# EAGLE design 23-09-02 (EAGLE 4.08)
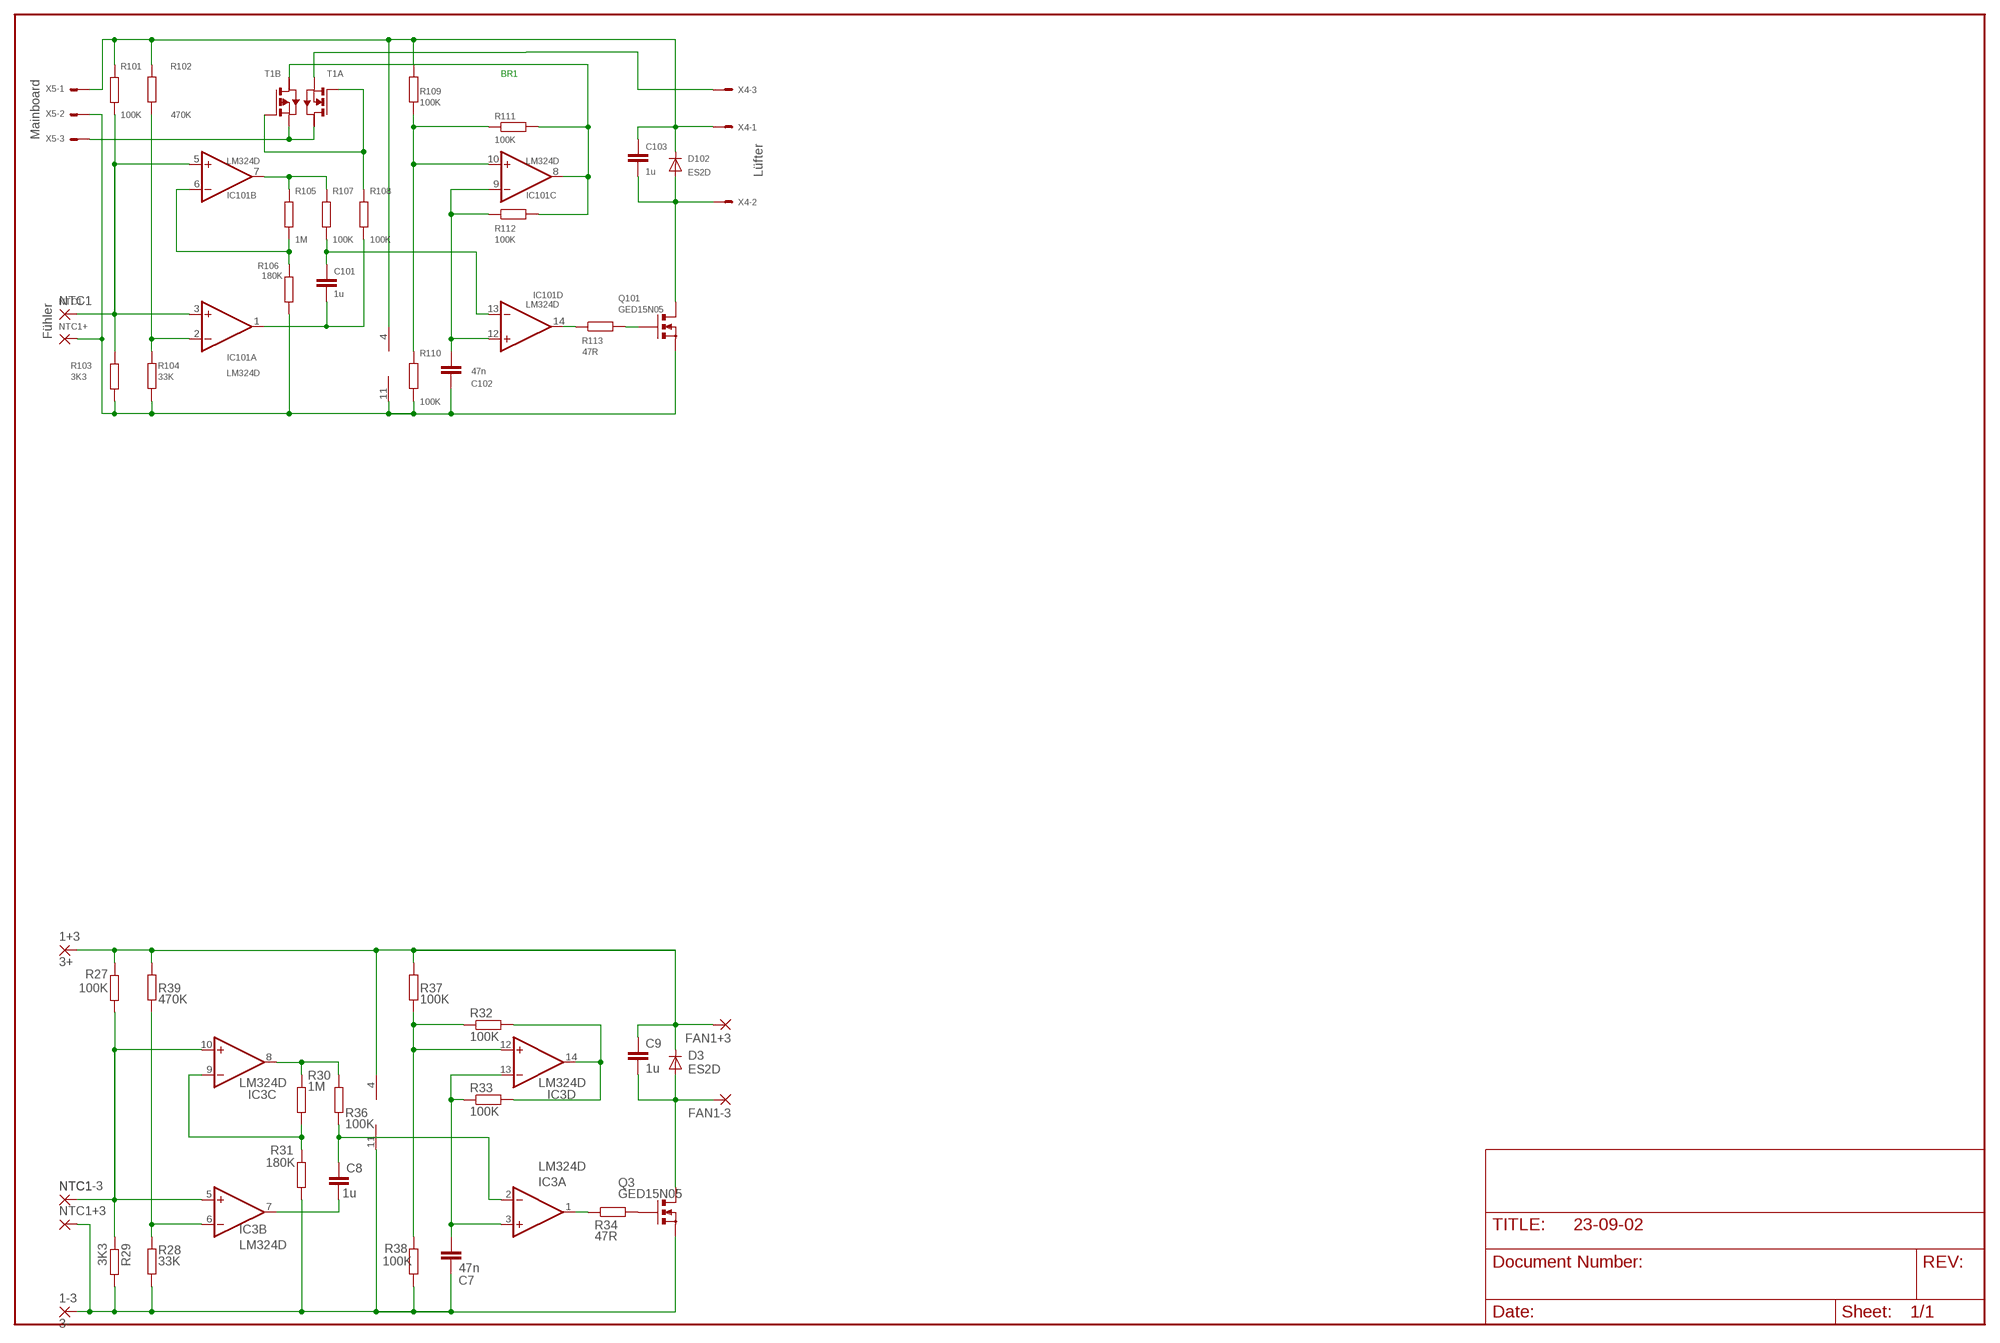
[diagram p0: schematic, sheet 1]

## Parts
1+3  3+  SMD2  [SMD2]
1-3  3-  SMD2  [SMD2]
BR1  BR  [C1206]
C7  47n  C-EUC0805  [C0805]
C8  1u  C-EU  [2220]
C9  1u  C-EU  [2220]
C101  1u  C-EU  [2220]
C102  47n  C-EUC1206  [C1206]
C103  1u  C-EU  [2220]
D3  ES2D  DIODE-SMB  [SMB]
D102  ES2D  DIODE-SMB  [SMB]
FAN1+3  SMD2  [SMD2]
FAN1-3  SMD2  [SMD2]
IC3  LM324D  [SO14]
IC101  LM324D  [SO14]
NTC1+  SMD2  [SMD2]
NTC1+3  SMD2  [SMD2]
NTC1-  NTC1  SMD2  [SMD2]
NTC1-3  NTC1  SMD2  [SMD2]
Q3  GED15N05  [TO252]
Q101  GED15N05  [TO252]
R27  100K  R-EU_M1206  [M1206]
R28  33K  R-EU_M1206  [M1206]
R29  3K3  R-EU_M1206  [M1206]
R30  1M  R-EU_R1206W  [R1206W]
R31  180K  R-EU_R1206W  [R1206W]
R32  100K  R-EU_M0805  [M0805]
R33  100K  R-EU_M0805  [M0805]
R34  47R  R-EU_M1206  [M1206]
R36  100K  R-EU_M1206  [M1206]
R37  100K  R-EU_M0805  [M0805]
R38  100K  R-EU_M0805  [M0805]
R39  470K  R-EU_M1206  [M1206]
R101  100K  R-EU_M1206  [M1206]
R102  470K  R-EU_M1206  [M1206]
R103  3K3  R-EU_M1206  [M1206]
R104  33K  R-EU_M1206  [M1206]
R105  1M  R-EU_R1206  [R1206]
R106  180K  R-EU_M1206  [M1206]
R107  100K  R-EU_M1206  [M1206]
R108  100K  R-EU_M1206  [M1206]
R109  100K  R-EU_M1206  [M1206]
R110  100K  R-EU_M1206  [M1206]
R111  100K  R-EU_M1206  [M1206]
R112  100K  R-EU_M1206  [M1206]
R113  47R  R-EU_M1206  [M1206]
T1  PN_MOSOP8  [MSOP8]
X4  53398-03  [53398-03]
X5  53398-03  [53398-03]

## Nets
N$2: T1.1(A:S) T1.3(B:D) X5.3
N$3: IC3.5(B:+IN) IC3.10(C:+IN) NTC1-3.1(P) R27.2 R29.1
N$4: C102.1 IC101.11(P:V-) NTC1+.1(P) Q101.S R103.2 R104.1 R106.2 R110.1 X5.2
N$24: C103.P$1 D102.C IC101.4(P:V+) R101.1 R102.2 R109.2 X4.1 X5.1
N$37: C103.P$2 D102.A Q101.D X4.2
N$44: IC101.3(A:+IN) IC101.5(B:+IN) NTC1-.1(P) R101.2 R103.1
N$46: C101.P$2 IC101.13(D:-IN) R107.2
N$47: IC101.8(C:OUT) R111.2 R112.2 T1.7(A:D)
N$64: C8.P$2 IC3.2(A:-IN) R36.2
N$66: C101.P$1 IC101.1(A:OUT) R108.2
N$72: IC3.6(B:-IN) R28.2 R39.1
N$73: C8.P$1 IC3.7(B:OUT)
N$74: IC3.8(C:OUT) R30.1 R36.1
N$75: IC3.9(C:-IN) R30.2 R31.1
N$76: IC3.14(D:OUT) R32.2 R33.2
N$77: IC3.12(D:+IN) R32.1 R37.1 R38.2
N$78: C7.2 IC3.3(A:+IN) IC3.13(D:-IN) R33.1
N$79: IC3.1(A:OUT) R34.1
N$81: Q3.G R34.2
N$82: BR1.1 T1.6(B:S)
N$83: 1+3.1(P) C9.P$1 D3.C FAN1+3.1(P) IC3.4(P:V+) R27.1 R37.2 R39.2
N$84: C9.P$2 D3.A FAN1-3.1(P) Q3.D
N$85: 1-3.1(P) C7.1 IC3.11(P:V-) NTC1+3.1(P) Q3.S R28.1 R29.2 R31.2 R38.1
N$86: BR1.2 X4.3
N$98: R108.1 T1.2(A:G) T1.5(B:G)
N$128: IC101.2(A:-IN) R102.1 R104.2
N$130: IC101.7(B:OUT) R105.1 R107.1
N$132: IC101.6(B:-IN) R105.2 R106.1
N$136: IC101.10(C:+IN) R109.1 R110.2 R111.1
N$138: IC101.14(D:OUT) R113.1
N$139: C102.2 IC101.9(C:-IN) IC101.12(D:+IN) R112.1
N$141: Q101.G R113.2
Unconnected: T1.4(B:D2) T1.8(A:D2)

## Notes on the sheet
- Mainboard
- Lüfter
- Fühler

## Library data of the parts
1+3 1-3 FAN1+3 FAN1-3 NTC1+ NTC1+3 NTC1- NTC1-3 = wirepad:SMD2: SMD PAD
BR1 = rcl:BR
C7-C9 C101-C103 = rcl:C-EU: CAPACITOR, European symbol
D3 D102 = diode:DIODE-: DIODE
IC3 IC101 = linear:LM324: OP AMP
Q3 Q101 = transistor-fet:GED15N05
R27-R34 R36-R39 R101-R113 = rcl:R-EU_: RESISTOR, European symbol
T1 = zetex:PN_MOSOP8: Dual MOS FET
X4 X5 = con-molex:53?-03: CONNECTOR wire to board 1.25 mm (.049 inch) pitch header

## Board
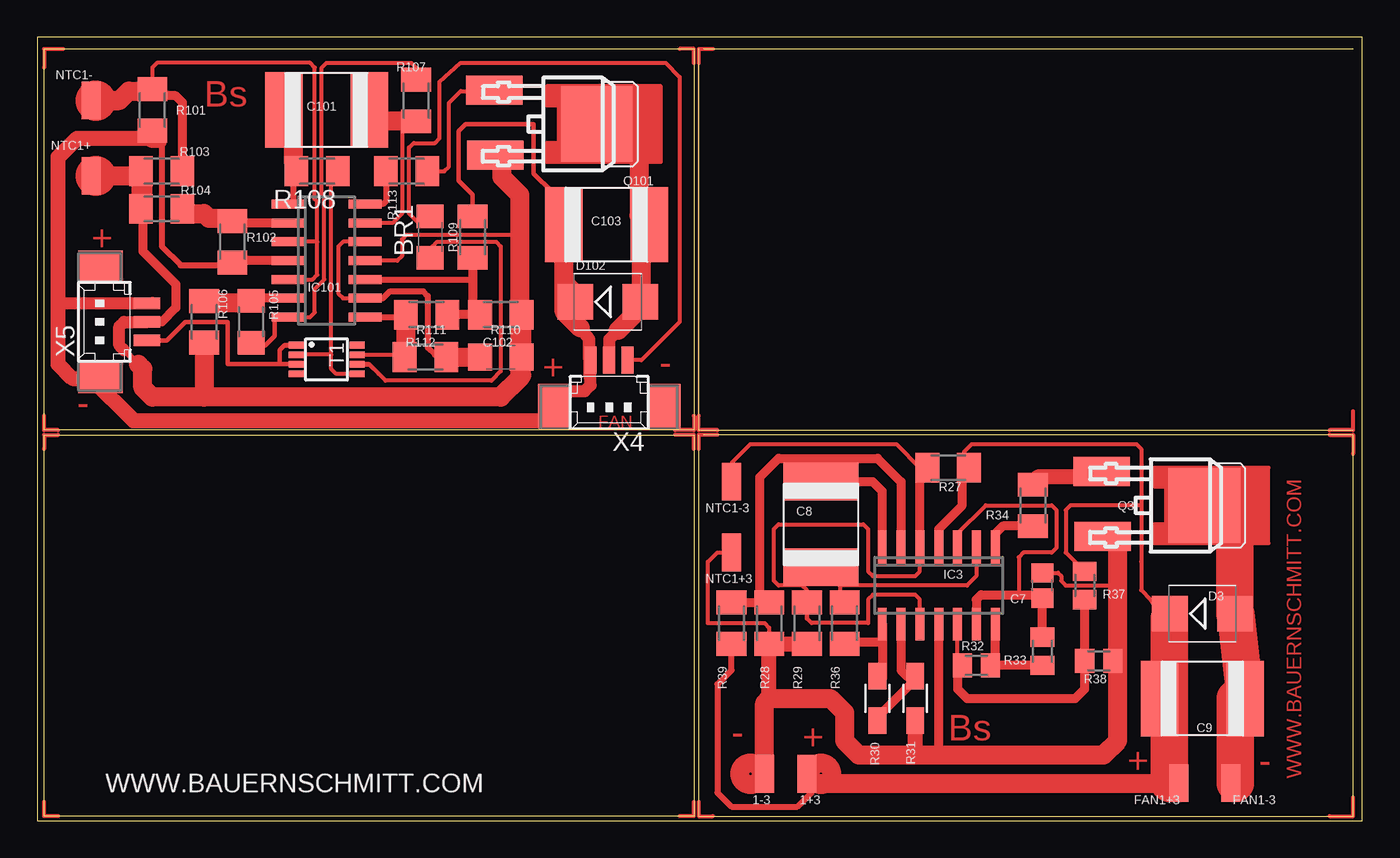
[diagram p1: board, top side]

Size 89.36 x 52.85 mm. Coordinates in mm from the lower left corner, seen from the top.
Outline: 44.92,52.07 88.73,52.07
Outline: 44.6,52.07 44.6,26.35 88.73,26.35
Outline: 44.6,26.03 44.6,0.31 88.73,0.31 88.73,26.03 44.92,26.03
Outline: 0,0 89.36,0 89.36,52.85 0,52.85 0,0
Outline: 44.28,26.03 44.28,0.31 0.47,0.31 0.47,26.03 44.28,26.03
Outline: 44.28,52.07 44.28,26.35 0.47,26.35 0.47,52.07 44.28,52.07
Copper layers used: Top

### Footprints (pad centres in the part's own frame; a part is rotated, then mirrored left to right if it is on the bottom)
SMD2 = smd 1.27 x 2.54: 1 0,0
C1206 = smd 1.6 x 1.8: 1 -1.4,0; 2 1.4,0
C0805 = smd 1.3 x 1.5: 1 -0.85,0; 2 0.85,0
2220 = smd 2.54 x 5.08: P$1 -2.885,0; P$2 2.885,0
SMB = smd 2.4 x 2.4: A 2.2,0; C -2.2,0
SO14 = smd 0.6 x 2.2: 1 -3.81,-2.6; 2 -2.54,-2.6; 3 -1.27,-2.6; 4 0,-2.6; 5 1.27,-2.6; 6 2.54,-2.6; 7 3.81,-2.6; 8 3.81,2.6; 9 2.54,2.6; 10 1.27,2.6; 11 0,2.6; 12 -1.27,2.6; 13 -2.54,2.6; 14 -3.81,2.6
TO252 = smd 5.08 x 2.54: D 0,6.032; GED15N05 0,3.747 | smd 1.016 x 0.508: G -2.032,-1.778; P$9 -2.032,-0.762; P$16 -2.032,-1.27; P$18 -2.032,-2.286; P$19 -2.032,-2.54; P$20 2.032,-0.762; P$21 2.032,-1.016; P$23 2.032,-2.032; P$24 2.032,-2.286; P$25 2.032,-2.54; S 2.032,-1.524 | smd 0.254 x 0.152: P$3 -2.54,-0.508; P$4 2.54,-0.508; P$5 -2.286,-0.508; P$6 -2.032,-0.508; P$7 -1.778,-0.508; P$10 2.286,-0.508; P$11 2.032,-0.508; P$12 1.778,-0.508; P$13 1.524,-0.508; P$15 -2.794,-0.508 | smd 1.93 x 3.81: P$8 -2.286,-2.032; P$14 2.095,-1.968
M1206 = smd 1.6 x 2: 1 -1.4,0; 2 1.4,0
R1206W = smd 1.8 x 1.2: 1 -1.499,0; 2 1.499,0
M0805 = smd 1.3 x 1.6: 1 -0.95,0; 2 0.95,0
R1206 = smd 1.6 x 1.803: 1 -1.422,0; 2 1.422,0
MSOP8 = smd 0.45 x 1: 1 -0.975,-2.05; 2 -0.325,-2.05; 3 0.325,-2.05; 4 0.975,-2.05; 5 0.975,2.05; 6 0.325,2.05; 7 -0.325,2.05; 8 -0.975,2.05
53398-03 = smd 0.8 x 1.8: 1 1.25,-2.5; 2 0,-2.5; 3 -1.25,-2.5 | smd 2.1 x 3: S1 3.75,0.625; S2 -3.75,0.625

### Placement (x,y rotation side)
1+3  51.9,3.17 0 top
1-3  49.05,3.17 0 top
BR1  26.5,39.37 90 top
C7  67.78,15.87 270 top
C8  52.86,20 270 top
C9  78.58,8.25 0 top
C101  19.52,47.94 0 top
C102  31.27,31.27 180 top
C103  38.39,40.2 0 top
D3  78.58,13.97 0 top
D102  38.48,35 0 top
FAN1+3  76.99,2.54 0 top
FAN1-3  80.48,2.54 0 top
IC3  60.79,15.87 180 top
IC101  19.52,37.78 270 top
NTC1+  3.65,43.49 0 top
NTC1+3  46.82,18.09 0 top
NTC1-  3.65,48.57 0 top
NTC1-3  46.82,22.86 0 top
Q3  73.81,21.27 270 top
Q101  32.85,46.98 270 top
R27  61.43,23.81 180 top
R28  49.36,13.33 90 top
R29  51.9,13.33 270 top
R30  56.67,8.25 270 top
R31  59.21,8.25 270 top
R32  63.33,10.47 0 top
R33  67.78,11.43 270 top
R34  67.15,21.27 90 top
R36  54.45,13.33 90 top
R37  70.64,15.87 90 top
R38  71.59,10.79 180 top
R39  46.82,13.33 270 top
R101  7.77,47.94 90 top
R102  13.17,39.05 270 top
R103  8.41,43.81 180 top
R104  8.41,41.27 0 top
R105  14.44,33.65 90 top
R106  11.27,33.65 270 top
R107  25.55,48.57 270 top
R108  18.89,43.81 180 top
R109  29.36,39.37 90 top
R110  31.27,34.13 180 top
R111  26.26,34.13 180 top
R112  26.19,31.27 180 top
R113  24.92,43.81 0 top
T1  19.52,31.11 270 top
X4  38.57,28.57 180 top
X5  4.92,33.65 90 top

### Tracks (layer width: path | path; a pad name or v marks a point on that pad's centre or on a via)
N$2
  Top 0.305: X5.3 8.74,32.4 10,33.65 12.85,33.65 12.85,30.79 16.34,30.79 | 17.62,30.79 17.3,30.79 | 16.34,31.74 16.66,32.06 17.62,32.06 17.59,32.09 T1.1 16.68,32.09 16.34,31.74 | 16.34,31.74 16.34,30.79 | 17.3,30.79 T1.3 | 16.34,30.79 17.3,30.79
N$3
  Top 0.254: R29.1 51.9,13.65 | NTC1-3.1 46.82,24.12 48.09,25.39 57.94,25.39 59.52,23.81 | 59.52,13.33 59.52,14.92 59.21,15.24 56.35,15.24 56.03,14.92 56.03,13.33 52.22,13.33 51.9,13.65 | 51.9,13.65 51.9,15.55 51.59,15.87 50,15.87 49.68,16.19 49.68,19.68 50,20 55.71,20 56.03,19.68 56.03,16.82 56.35,16.5 59.21,16.5 59.52,16.82 59.52,18.41
  Top 0.61: IC3.10 59.52,13.33 | IC3.5 59.52,18.73 | R27.2 59.52,23.81 IC3.5 | IC3.5 59.52,18.41
N$4
  Top 0.254: 32.54,39.52 24.92,39.52 24.6,39.21 24.6,38.1 24.28,37.78 IC101.11
  Top 0.406: 32.54,39.52 32.85,38.73 32.54,38.73 | 22.06,37.78 IC101.11 | 5.87,31.74 6.82,30.79
  Top 0.61: 7.14,41.27 7.14,38.41 9.36,36.19 9.36,34.6 8.41,33.65 7.46,33.65
  Top 0.813: 5.87,33.65 X5.2 7.46,33.65 5.87,33.65 | 5.87,33.65 5.55,33.33 5.55,32.06 5.87,31.74
  Top 1.016: R106.2 11.27,32.38
  Top 1.27: R103.2 7.01,41.78 6.82,41.59 7.01,41.4 R104.1 7.14,41.27 7.14,43.49 NTC1+.1 | Q101.S 31.33,43.43 32.54,42.22 32.54,39.52 | 32.54,39.52 32.54,38.73 32.54,31.43 | C102.1 32.67,34.41 32.54,34.29 32.67,34.16 R110.1 | 31.27,28.57 11.27,28.57 | 11.27,32.38 11.27,28.57 | 11.27,28.57 7.77,28.57 | 32.54,31.43 32.54,29.84 | 32.54,31.43 C102.1 | 32.54,29.84 32.67,30.03 32.67,30.61 | C102.1 32.67,30.61 | 32.67,30.61 32.54,29.84 | 32.54,39.52 32.54,29.84 | 32.54,29.84 31.27,28.57 | 31.27,28.57 7.77,28.57 | 7.77,28.57 7.14,29.2 7.14,30.47 6.82,30.79
N$6
  Top 0: 0.47,52.07 44.28,52.07 44.28,26.35 0.47,26.35 0.47,52.07
  Top 0.254: 0.47,50.8 0.47,52.07 1.74,52.07 | 44.28,27.3 44.28,26.35 43.01,26.35
N$11
  Top 0: 44.6,52.07 44.6,26.35 88.73,26.35
  Top 0.254: 45.55,52.07 44.6,52.07 44.6,51.11 | 87.15,26.35 88.73,26.35 88.73,27.62
N$12
  Top 0.254: 44.28,51.11 44.28,52.07 43.33,52.07
N$14
  Top 0.254: 44.28,25.08 44.28,26.03 43.01,26.03
N$16
  Top 0.254: 45.87,26.35 44.6,26.35 44.6,27.3
N$18
  Top 0: 44.6,26.03 44.6,0.31 88.73,0.31 88.73,26.03 44.6,26.03
  Top 0.254: 45.87,26.03 44.6,26.03 44.6,25.08 | 87.15,0.31 88.73,0.31 88.73,1.58
N$21
  Top 0.254: 44.6,1.27 44.6,0.31 45.55,0.31
N$22
  Top 0.254: 1.42,0.31 0.47,0.31 0.47,1.27
N$23
  Top 0: 44.28,0.31 44.28,26.03 0.47,26.03 0.47,0.31
  Top 0.254: 0.47,25.08 0.47,26.03 1.42,26.03 | 44.28,1.27 44.28,0.31 43.33,0.31
N$24
  Top 0.254: 8.41,45.72 8.41,46.03 8.09,46.03 | 7.77,34.92 7.75,34.9 X5.1 | 37.3,32.38 37.32,32.38 37.22,32.48 | 13.17,37.46 R102.2
  Top 0.305: R109.2 29.36,42.22 28.41,43.18 28.41,46.51 28.89,46.98 33.49,46.98 33.49,43.65 34.76,42.38 34.76,40.95 35.08,40.64 34.97,40.53 34.91,40.53
  Top 0.406: 8.41,45.72 8.41,38.73 9.68,37.46 13.17,37.46
  Top 0.61: 8.09,46.03 8.41,45.72 | R102.2 13.17,37.78 IC101.4
  Top 0.813: 37.32,31.09 X4.1 | 37.32,31.09 37.22,31.09 37.22,32.48 | 37.22,32.48 36.61,33.24 | 37.22,32.48 37.22,29.99 | 37.32,31.09 37.32,29.38 36.92,28.98 35.39,28.98 35.39,28.89 | 1.42,34.92 7.77,34.92
  Top 1.016: 2.69,46.03 7.77,46.03 | 35.39,28.89 35.08,28.57 35.08,27.62 34.44,26.98 6.5,26.98 3.65,29.84 2.38,29.84 1.42,30.79 1.42,34.92 1.42,44.76 2.69,46.03 | 2.69,46.03 8.09,46.03
  Top 1.27: 8.09,46.03 7.77,46.03 7.96,46.22 R101.1 | C103.P$1 34.87,40.62 34.94,40.56 34.91,40.53 35.55,40.53 35.55,36.29 | 35.55,36.29 35.55,35.53 36.16,35.53 36.16,35.63 D102.C 36.28,35.56 35.55,36.29 | 36.61,33.24 35.55,34.31 35.55,36.29
N$25
  Top 0.254: 1.42,26.35 0.47,26.35 0.47,27.3
N$36
  Top 0.254: 87.15,26.03 88.73,26.03 88.73,24.76
N$37
  Top 0.813: X4.2 38.59,31.07 38.59,32.48 39.2,33.09
  Top 1.27: Q101.D 40.58,47.94 40.58,40.84 C103.P$2 40.73,40.84 40.73,35.68 | 40.73,35.68 40.73,35.63 D102.A 40.68,35.63 40.73,35.68 | 39.2,33.09 40.73,34.62 40.73,35.68
N$44
  Top 0.254: IC101.5 18.57,36.51 18.89,36.83 18.89,39.05 | 18.89,39.05 IC101.3 | 18.89,39.05 | 18.89,39.05 18.89,41.75 18.73,41.91 18.73,50.8 18.41,51.11 8.09,51.11 7.77,50.8 7.77,49.53
  Top 0.61: R103.1 9.81,48.44 9.36,48.89 5.87,48.89 3.96,48.89 NTC1-.1
  Top 1.27: R101.2 7.77,49.53 7.46,49.21 6.19,49.21 5.87,48.89 5.55,48.57 NTC1-.1
N$46
  Top 0.254: C101.P$2 22.41,47.33 22.38,47.3 24.6,47.3 24.6,40.95 23.96,40.32 IC101.13 21.74,40.32
  Top 0.406: IC101.13 22.06,40.32
  Top 1.27: C101.P$2 22.41,47.65 22.38,47.62 22.82,47.17 R107.2
N$47
  Top 0.254: 24.91,32.07 24.91,31.75 24.92,31.74 24.61,31.43 T1.7
  Top 0.406: 24.91,32.07 24.92,32.06 24.92,33.97 | R111.2 24.92,34.29 24.92,33.97 | IC101.8 24.92,33.97 | 24.92,33.97 24.92,31.74 24.92,31.43
  Top 1.27: R112.2 24.92,31.43 24.86,31.48 R111.2
N$64
  Top 0.254: IC3.2 63.33,16.5 62.7,15.87 54.13,15.87 | 54.13,17.46 52.86,17.46 C8.P$2 52.88,17.43 54.1,17.43 54.13,17.46 | 54.13,17.46 54.13,15.87 | R36.2 54.45,14.28 54.13,14.6 54.13,15.87
N$66
  Top 0.254: 17.3,47.94 C101.P$1
  Top 0.406: IC101.1 17.3,41.59 17.3,43.49 17.62,43.81 R108.2
  Top 1.27: R108.2 17.3,44.45 17.3,47.94
N$72
  Top 0.61: 58.25,18.41 IC3.6 58.25,22.86 56.67,24.44 50,24.44 48.73,23.17 48.73,14.6 | R39.1 48.6,14.73 48.73,14.6 | 48.73,14.6 R28.2
N$73
  Top 0.61: IC3.7 56.98,22.22 56.35,22.86 52.54,22.86 C8.P$1
N$74
  Top 0.61: 56.98,13.33 IC3.8 56.98,12.06 | 56.98,12.06 56.98,9.52 56.9,9.43 R30.1 56.67,9.52 56.98,9.84 56.98,12.06 | R36.1 54.45,12.06 56.98,12.06
N$75
  Top 0.61: R30.2 56.67,6.98 59.02,9.33 R31.1 59.21,9.2 58.25,10.16 IC3.9
N$76
  Top 0.61: 64.61,10.47 R32.2 | R33.2 64.61,10.47 | 64.61,10.47 IC3.14
N$77
  Top 0.254: R32.1 62.06,10.79 IC3.12
  Top 0.61: 62.06,10.79 62.06,8.89 62.7,8.25 70,8.25 70.64,8.89 70.64,10.47 70.64,10.48 R38.2 R37.1
N$78
  Top 0.254: 62.06,18.41 IC3.3 62.06,19.36 63.97,21.27 68.42,21.27 68.73,20.95 68.73,18.41 68.42,18.09 66.51,18.09 66.19,17.77 66.19,15.24 | 66.19,15.24 67.78,15.24 | 66.19,15.24 63.65,15.24
  Top 0.61: R33.1 C7.2 67.78,15.24 63.65,15.24 63.33,14.92 IC3.13
N$79
  Top 0.61: R34.1 65.11,19.87 64.61,19.36 IC3.1 64.61,18.41
N$81
  Top 1.016: Q3.G 71.91,23.17 67.46,23.17 67.15,22.86 R34.2
N$82
  Top 0.254: 23.01,30.16 22.39,30.79 T1.6 21.73,30.79 21.74,30.79 22.38,30.79 23.49,29.68 30.63,29.68 31.27,30.32 31.27,38.73 30.95,39.05 26.98,39.05 26.66,38.73 BR1.1
N$83
  Top 0.254: 75.08,14.92 74.45,15.55 74.45,17.46 74.45,21.27 | 75.08,14.92 75.72,13.96 | R27.1 62.51,24.89 63.02,25.39 74.13,25.39 74.45,25.08 74.45,21.27 | R39.2 46.82,11.43 | R37.2 69.37,18.09 69.37,20.95 69.69,21.27 74.45,21.27 | D3.C 76.35,13.65 75.08,14.92
  Top 0.406: 52.22,2.54 52.22,1.9 51.27,0.95 46.82,0.95 45.87,1.9 45.87,9.2 46.82,10.16 R39.2
  Top 0.61: IC3.4 60.79,19.68 62.38,21.27 62.38,23.49 62.51,23.62 R27.1
  Top 1.27: 76.35,2.54 52.22,2.54 51.9,2.54 1+3.1 | 76.35,2.54 76.38,2.51 76.64,2.51 FAN1+3.1 76.35,2.54 | C9.P$1 76.33,7.96 76.35,7.93 76.35,2.54 | 76.35,13.65 76.38,13.67 D3.C
  Top 2.54: 76.35,2.54 76.35,13.65
N$84
  Top 1.27: FAN1-3.1 80.8,2.54 | 80.8,7.93 80.83,7.96 C9.P$2 | 80.8,13.97 D3.A
  Top 2.54: 80.8,8.25 80.8,7.93 80.8,2.54 | C9.P$2 80.83,13.94 80.8,13.97 | Q3.D 80.8,20.95 80.78,20.93 D3.A
N$85
  Top 0.254: NTC1+3.1 45.87,18.09 45.24,17.46 45.24,13.33 49.05,13.33 49.36,13.01 49.36,11.43 | 49.36,11.43 R28.1 | 49.36,11.43 49.18,11.93 | C7.1 68.84,16.72 69.05,16.5 69.05,16.19 69.37,15.87 72.86,15.87 73.18,16.19 73.18,19.04
  Top 0.61: 59.21,5.71 R31.2 | 60.79,13.33 IC3.11 60.79,4.44
  Top 1.016: 55.4,4.44 59.21,4.44 | 59.21,4.44 60.79,4.44 | 59.21,4.44 59.21,5.71 | 59.21,4.44 71.91,4.44 | 49.36,8.25 R28.1 | 49.18,11.93 R29.2
  Top 1.27: 1-3.1 49.05,7.93 49.36,8.25 53.49,8.25 54.45,7.3 54.45,5.39 55.4,4.44 71.91,4.44 72.86,5.39 72.86,10.79 | R38.1 72.86,10.79 | Q3.S 72.99,19.23 72.86,19.36 72.86,10.79
N$86
  Top 0.254: X4.3 40.75,31.07 43.33,33.65 43.33,50.16 42.38,51.11 28.57,51.11 27.14,49.84 27.14,46.03 26.82,45.72 25.39,45.72 25.08,45.4 25.08,40.95 25.71,40.32 26.5,40.95 BR1.2 26.5,40.64
N$98
  Top 0.254: 19.84,30.47 19.84,31.43 17.62,31.43 17.61,31.43 T1.2 | T1.5 20.18,30.13 19.84,30.47 | R108.1 20.47,43.81 19.84,43.18 19.84,30.47
N$128
  Top 0.61: R102.1 13.17,40.32 IC101.2
  Top 1.27: R104.2 9.81,41.14 10,40.95 11.27,40.95 11.58,40.64 12.54,40.64 12.85,40.32 12.98,40.45 R102.1
N$130
  Top 0.254: R107.1 25.55,50.8 25.23,51.11 19.52,51.11 19.2,50.8 19.2,42.22 19.36,42.06 19.36,36.51 18.72,35.87 18.72,34.29 18.4,33.97 16.98,33.97 | 16.98,33.97 IC101.7 | 16.03,33.97 16.98,33.97
  Top 0.305: 16.03,33.97 16.03,32.7 15.39,32.06 14.12,32.06
  Top 0.61: 14.12,32.06 R105.1
N$132
  Top 0.61: 14.12,34.92 R105.2 14.61,35.07 14.76,34.92 15.08,35.24 IC101.6
  Top 1.27: R106.1 11.27,34.92 14.12,34.92
N$136
  Top 0.406: IC101.10 29.36,36.51
  Top 0.61: 29.36,37.78 29.18,37.97 R109.1 29.36,37.78 | 29.36,37.78 29.36,36.51 29.36,34.6 29.68,34.29 R110.2 R111.1
N$138
  Top 0.406: R113.1 23.52,41.78 23.33,41.59 IC101.14
N$139
  Top 0.254: IC101.12 20.63,39.05 20.31,38.73 20.31,35.55 20.63,35.24 IC101.9
  Top 0.406: IC101.9 23.33,35.24 23.81,35.71 26.03,35.71 26.35,35.4 26.35,31.9 26.82,31.43 R112.1
  Top 1.27: R112.1 C102.2
N$141
  Top 0.254: Q101.G 32.22,49.84 31.9,49.21 28.57,49.21 27.78,48.41 27.78,44.13 27.46,43.81 R113.2
(copper drawn outside any net)
  shapes: Top circle x4

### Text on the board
Top: Bs | + | + | - | - | FAN | Bs | - | + | + | - | WWW.BAUERNSCHMITT.COM
tNames: WWW.BAUERNSCHMITT.COM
